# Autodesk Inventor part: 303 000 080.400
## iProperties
Created: 2007-08
Part Number: 303 000 080.400
Material: 1.4305 X10 CrNiS 18-9
Description: ENSAT-SD M8
Document SubType Name: Modellieren
Designer: Administrator
Manufacturer: Standard
Standards Organization: Custom
Mass: 3.84199 g
Surface Area: 7.08808 cm^2
Volume: 0.488802 cm^3
Density: 7.86 g/cm^3
Author: Administrator
Comments: Kerbkonus
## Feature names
1. Extrusion2
2. Bohrung1 [Hole]
3. Extrusion3
